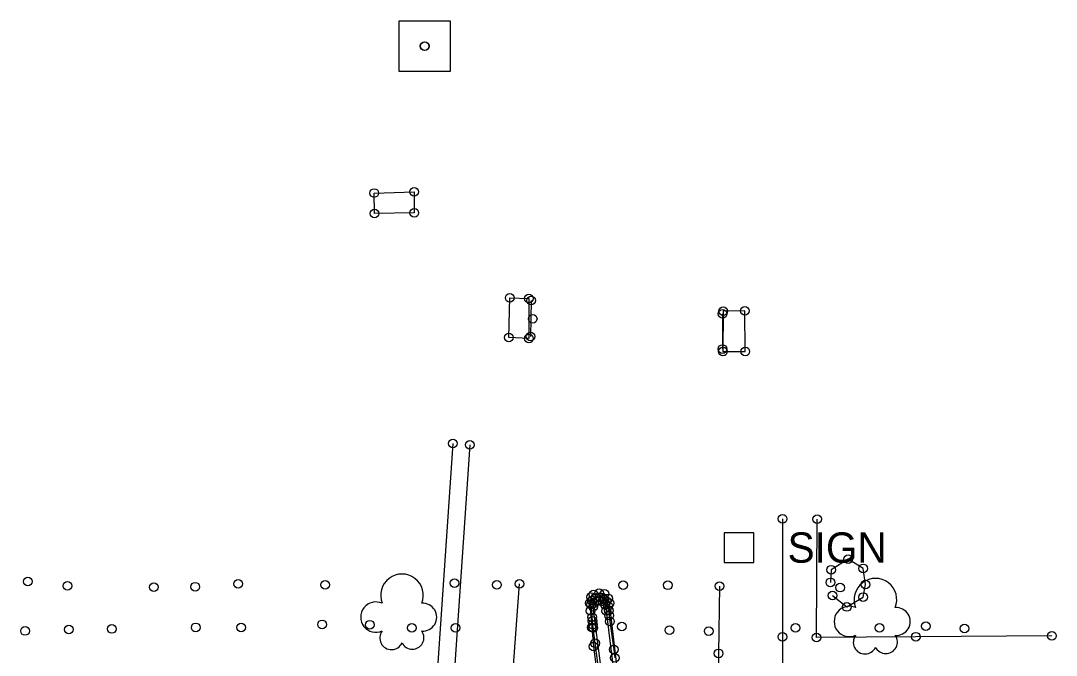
# Model space of a CAD drawing. Extents: x 20503438 to 20508873, y 7964251 to 7984667.
# Drawn here: x 20507965.8 to 20508204.6, y 7970826.2 to 7970972.7 of the extents above; entities that cross this region are included whole.
import ezdxf

# ---------------------------------------------------------------- set-up
doc = ezdxf.new("R2010")
doc.units = 0
for name, color, linetype in [('Default', 7, 'Continuous'), ('SurConcreteSlab', 7, 'Continuous'), ('SurControl', 7, 'Continuous'), ('SurEdgeCurb', 7, 'Continuous'), ('SurEdgeRoadPaved', 7, 'Continuous'), ('SurEdgeSidewalk', 7, 'Continuous'), ('SurMiscStructureLine', 7, 'Continuous'), ('SurNaturalCells', 7, 'Continuous'), ('SurPointsNonDTM', 7, 'Continuous'), ('SurRoadPoints', 7, 'Continuous'), ('SurSurveyPoints', 7, 'Continuous')]:
    doc.layers.add(name, color=color, linetype=linetype)

msp = doc.modelspace()

# ---------------------------------------------------------------- linework, layer by layer
at = {"layer": 'Default'}
msp.add_line((20508058.96, 7970966.8), (20508058.96, 7970966.8), dxfattribs=at)
at = {"layer": 'SurConcreteSlab'}
for points in [[(20508056.53, 7970933.17), (20508056.56, 7970928.33), (20508047.39, 7970928.17), (20508047.33, 7970932.91)], [(20508083.01, 7970899.32), (20508078.36, 7970899.58), (20508078.56, 7970908.71), (20508082.97, 7970908.56)], [(20508127.76, 7970896.34), (20508132.91, 7970896.34), (20508132.8, 7970905.69), (20508127.8, 7970905.63)]]:
    msp.add_lwpolyline(points, close=True, dxfattribs=at)
msp.add_lwpolyline([(20508103.11, 7970796.34), (20508097.78, 7970837.4), (20508098.06, 7970838.21), (20508098.58, 7970838.71), (20508099.2, 7970838.8), (20508099.97, 7970838.59), (20508100.61, 7970837.86), (20508100.82, 7970836.46), (20508109.87, 7970762.52)], dxfattribs=at)
at = {"layer": 'SurControl'}
for p, q in [((20508053.08, 7970960.92), (20508053.08, 7970972.68)), ((20508053.08, 7970972.68), (20508064.84, 7970972.68)), ((20508064.84, 7970972.68), (20508064.84, 7970960.92)), ((20508064.84, 7970960.92), (20508053.08, 7970960.92))]:
    msp.add_line(p, q, dxfattribs=at)
at = {"layer": 'SurEdgeCurb'}
for points in [[(20508083.52, 7970908.1), (20508083.37, 7970899.81)], [(20508127.68, 7970905.03), (20508127.64, 7970896.9)], [(20508104.09, 7970816.8), (20508101.55, 7970838.26), (20508101.25, 7970839.35), (20508100.43, 7970840.39), (20508099.17, 7970840.52), (20508097.87, 7970840.26), (20508097.34, 7970839.65), (20508097.04, 7970838.22), (20508097.19, 7970836.5), (20508097.53, 7970832.6), (20508097.91, 7970828.23), (20508103.64, 7970783.23)], [(20508098.94, 7970823.85), (20508098.29, 7970828.97), (20508097.84, 7970832.56), (20508097.75, 7970833.29), (20508097.64, 7970834.17), (20508097.58, 7970834.97), (20508097.36, 7970837.9), (20508097.55, 7970838.82), (20508098.33, 7970839.5), (20508099.36, 7970839.58), (20508100.31, 7970839.32), (20508100.89, 7970838.7), (20508101.3, 7970837.55), (20508101.41, 7970836.54), (20508101.53, 7970835.38), (20508101.69, 7970833.99), (20508102.56, 7970827.54), (20508102.81, 7970825.63)]]:
    msp.add_lwpolyline(points, dxfattribs=at)
at = {"layer": 'SurEdgeRoadPaved'}
for points in [[(20508004.64, 7970575.98), (20508007.59, 7970576.24), (20508010.15, 7970576.78), (20508012.71, 7970577.32), (20508023.73, 7970580.41), (20508026.58, 7970581.33), (20508029.43, 7970582.25), (20508043.66, 7970586.87), (20508052.12, 7970591.56), (20508057.59, 7970595.51), (20508062.67, 7970600.63), (20508065.66, 7970604.97), (20508069.09, 7970611.13), (20508071.43, 7970616.3), (20508072.6, 7970620.21), (20508073.47, 7970624.24), (20508074.25, 7970633.1), (20508074.72, 7970680.34), (20508074.97, 7970737.67), (20508075.09, 7970747.61), (20508075.12, 7970749.94), (20508075.43, 7970766.91), (20508076.47, 7970783.01), (20508080.81, 7970842.69)], [(20508126.95, 7970842.14), (20508126.76, 7970826.65), (20508126.73, 7970824.07), (20508126.8, 7970818.79), (20508126.9, 7970810.87), (20508127.5, 7970802.09), (20508127.7, 7970799.17), (20508128.55, 7970785.48), (20508129.03, 7970782.71), (20508129.77, 7970781.14), (20508131.16, 7970780.45), (20508132.8, 7970780.27), (20508134.32, 7970780.62), (20508136.49, 7970782.18), (20508139.4, 7970784.57), (20508141.37, 7970786.17)]]:
    msp.add_lwpolyline(points, dxfattribs=at)
at = {"layer": 'SurEdgeSidewalk'}
for points in [[(20508065.45, 7970875.11), (20508061.91, 7970823.31), (20508058.11, 7970771.65), (20508057.66, 7970725.29), (20508057.57, 7970688.87), (20508054.09, 7970657.04), (20508050.99, 7970628.26), (20508043.75, 7970610.25), (20508036.32, 7970592.17), (20508028.13, 7970591.62), (20508019.27, 7970591.01), (20508019.15, 7970583.11), (20508026.86, 7970581.98)], [(20508069.38, 7970874.8), (20508065.82, 7970823.03), (20508062.04, 7970771.3), (20508061.58, 7970725.29), (20508061.4, 7970688.47), (20508058, 7970656.9), (20508054.87, 7970627.29), (20508047.37, 7970608.68), (20508040.75, 7970592.45), (20508053.1, 7970593.13)], [(20508141.52, 7970857.69), (20508141.46, 7970830.46), (20508141.56, 7970807.74), (20508141.44, 7970797.89), (20508139.87, 7970786.4), (20508141.29, 7970786.96), (20508145.79, 7970789.47), (20508150.05, 7970791.29), (20508150.97, 7970791.83), (20508149.75, 7970798.22), (20508149.41, 7970808.04), (20508149.33, 7970820.39), (20508172.37, 7970820.58), (20508203.46, 7970820.93)], [(20508203.64, 7970830.72), (20508172.24, 7970830.5), (20508149.32, 7970830.31), (20508149.48, 7970857.64)]]:
    msp.add_lwpolyline(points, dxfattribs=at)
at = {"layer": 'SurMiscStructureLine'}
msp.add_lwpolyline([(20508153, 7970840.03), (20508156.3, 7970837.36), (20508160.09, 7970839.65), (20508160.65, 7970842.55), (20508160.08, 7970846.27), (20508156.62, 7970848.41), (20508152.7, 7970845.96), (20508152.53, 7970843.04)], dxfattribs=at)
at = {"layer": 'SurNaturalCells'}
for centre, radius, start, end in [((20508053.72, 7970840.04), 4.92, 338.2051, 201.7949), ((20508162.93, 7970839.04), 4.92, 338.2051, 201.7949), ((20508047.7, 7970835.01), 3.51, 65.4824, 294.5175), ((20508058.52, 7970835.01), 3.21, 265.9982, 94.0018), ((20508156.91, 7970834.01), 3.51, 65.4824, 294.5175), ((20508167.73, 7970834.01), 3.21, 265.9982, 94.0018), ((20508051.29, 7970830.19), 2.68, 142.7501, 335.3223), ((20508056.11, 7970830.27), 2.67, 206.5242, 35.4033), ((20508160.5, 7970829.19), 2.68, 142.7501, 335.3223), ((20508165.32, 7970829.27), 2.67, 206.5242, 35.4033)]:
    msp.add_arc(centre, radius, start, end, dxfattribs=at)
at = {"layer": 'SurPointsNonDTM'}
for centre in [(20508156.62, 7970848.41), (20508152.7, 7970845.96), (20508160.08, 7970846.27), (20508152.53, 7970843.04), (20508160.65, 7970842.55), (20508153, 7970840.03), (20508160.09, 7970839.65), (20508156.3, 7970837.36)]:
    msp.add_circle(centre, 1, dxfattribs=at)
at = {"layer": 'SurRoadPoints'}
msp.add_lwpolyline([(20508131.45, 7970847.65), (20508131.45, 7970847.65), (20508134.88, 7970847.65), (20508134.88, 7970854.51), (20508128.02, 7970854.51), (20508128.02, 7970847.65), (20508131.45, 7970847.65)], dxfattribs=at)
at = {"layer": 'SurSurveyPoints'}
for centre in [(20508058.94, 7970966.81), (20508058.96, 7970966.79), (20508058.96, 7970966.79), (20508058.97, 7970966.79), (20508047.33, 7970932.91), (20508056.53, 7970933.17), (20508047.39, 7970928.17), (20508056.56, 7970928.33), (20508078.56, 7970908.71), (20508082.97, 7970908.56), (20508083.52, 7970908.1), (20508127.8, 7970905.63), (20508132.8, 7970905.69), (20508083.86, 7970903.86), (20508127.68, 7970905.03), (20508078.36, 7970899.58), (20508083.01, 7970899.32), (20508083.37, 7970899.81), (20508127.64, 7970896.9), (20508127.76, 7970896.34), (20508132.91, 7970896.34), (20508065.45, 7970875.11), (20508069.38, 7970874.8), (20508141.52, 7970857.69), (20508149.48, 7970857.64), (20507967.39, 7970843.26), (20507976.54, 7970842.24), (20507996.46, 7970841.93), (20508006.04, 7970842.04), (20508015.95, 7970842.68), (20508036, 7970842.49), (20508065.82, 7970842.84), (20508075.62, 7970842.45), (20508080.81, 7970842.69), (20508104.75, 7970842.38), (20508115.05, 7970842.37), (20508126.95, 7970842.14), (20508154.77, 7970841.82), (20508097.34, 7970839.65), (20508097.55, 7970838.82), (20508097.87, 7970840.26), (20508098.33, 7970839.5), (20508098.58, 7970838.71), (20508099.17, 7970840.52), (20508099.2, 7970838.8), (20508099.36, 7970839.58), (20508099.97, 7970838.59), (20508100.31, 7970839.32), (20508100.43, 7970840.39), (20508100.89, 7970838.7), (20508101.25, 7970839.35), (20508097.04, 7970838.22), (20508097.19, 7970836.5), (20508097.36, 7970837.9), (20508097.78, 7970837.4), (20508098.06, 7970838.21), (20508100.61, 7970837.86), (20508100.82, 7970836.46), (20508101.3, 7970837.55), (20508101.41, 7970836.54), (20508101.55, 7970838.26), (20508097.58, 7970834.97), (20508097.64, 7970834.17), (20508101.53, 7970835.38), (20508101.69, 7970833.99), (20507966.77, 7970831.82), (20507976.85, 7970832.15), (20507986.81, 7970832.29), (20508006.13, 7970832.65), (20508016.64, 7970832.64), (20508035.28, 7970833.34), (20508046.29, 7970833.27), (20508056, 7970832.54), (20508066.06, 7970832.56), (20508097.53, 7970832.6), (20508097.75, 7970833.29), (20508097.84, 7970832.56), (20508104.45, 7970832.84), (20508115.39, 7970832.03), (20508124.46, 7970831.78), (20508144.49, 7970832.57), (20508163.85, 7970832.57), (20508174.53, 7970832.95), (20508183.46, 7970832.38), (20508098.29, 7970828.97), (20508141.46, 7970830.46), (20508149.32, 7970830.31), (20508172.24, 7970830.5), (20508203.64, 7970830.72), (20508097.91, 7970828.23), (20508102.56, 7970827.54), (20508126.76, 7970826.65), (20508102.81, 7970825.63)]:
    msp.add_circle(centre, 1, dxfattribs=at)

# ---------------------------------------------------------------- texts
at = {"layer": 'SurRoadPoints'}
msp.add_text('SIGN', height=6.995, rotation=360, dxfattribs=at).set_placement((20508142.66, 7970847.58))

doc.saveas('drawing.dxf')
